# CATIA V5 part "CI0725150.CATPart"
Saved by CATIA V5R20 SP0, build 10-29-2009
Part number: CI0725150
Bounding box of the stored display mesh (mm): x -24 to 24, y -20.111 to 184.5, z -24.221 to 28.662
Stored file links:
  C:\Users\Raffaele\Desktop\3D X SITO CF\BOLEX\19-INCLINED ASSEMBLY REF_CI\CI0725150.CATPart
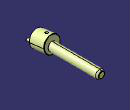
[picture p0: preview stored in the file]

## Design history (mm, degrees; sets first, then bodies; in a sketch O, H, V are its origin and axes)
Set1
  DatumSurface1 to DatumSurface16 "MANIFOLD_SOLID_BREP #393"
  DatumSurface17 to DatumSurface39 "MANIFOLD_SOLID_BREP #1138"
Body1 (main body)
